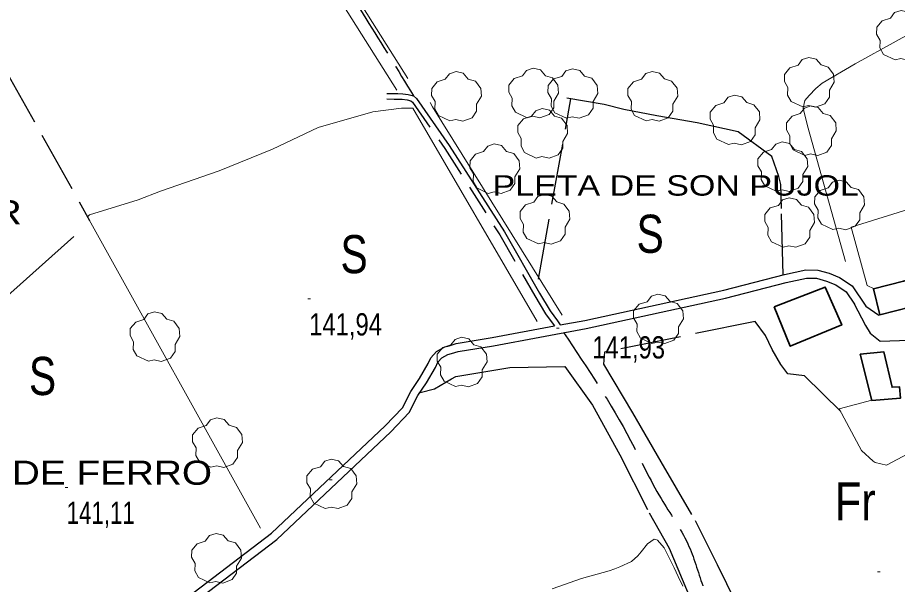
# Model space of a CAD drawing. Extents: x -807245 to 6129983, y -54972206 to 262146364.
# Drawn here: x 488741 to 489087.2, y 4383619.9 to 4383842.8 of the extents above; entities that cross this region are included whole.
import ezdxf
from ezdxf.enums import TextEntityAlignment as Align

# ---------------------------------------------------------------- set-up
doc = ezdxf.new("R2010")
doc.units = 0
doc.header["$LTSCALE"] = 4
doc.linetypes.add('LONG_DASHED', pattern=[7.5, 6, -1.5])
doc.linetypes.add('MEDIUM_DASHED', pattern=[4.5, 3, -1.5])
for name, color, linetype, lineweight in [('25', 7, 'LONG_DASHED', 25), ('27', 7, 'Continuous', 25), ('29', 7, 'Continuous', 13), ('38', 7, 'Continuous', 25), ('47', 7, 'Continuous', 35), ('51', 7, 'Continuous', 13), ('7', 7, 'Continuous', 13), ('9', 7, 'Continuous', 13)]:
    doc.layers.add(name, color=color, linetype=linetype, lineweight=lineweight)
doc.layers.add('31', color=7, linetype='Continuous')
doc.layers.add('5', color=7, linetype='Continuous')

msp = doc.modelspace()

# ---------------------------------------------------------------- linework, layer by layer
at = {"layer": '25'}
msp.add_line((488946.01, 4383739.92), (488958.62, 4383810.82), dxfattribs=at)
for points in [[(488581.61, 4383826.5), (488585.47, 4383840.65), (488589.08, 4383847.74), (488688.78, 4383900.02), (488691.79, 4383901.19), (488769.37, 4383763.08)], [(489042.16, 4383741.69), (489041.52, 4383767.79), (489041.33, 4383777.17), (489040.47, 4383780.34), (489037.71, 4383788.17), (489024.46, 4383797.92), (489008.37, 4383801.41), (488992.57, 4383804.14), (488979.55, 4383806.69), (488971.84, 4383808.65), (488957.09, 4383811.07)], [(489064.84, 4383687.92), (489050.6, 4383701.9), (489044.09, 4383702.72), (489041.35, 4383706.35), (489037.89, 4383712.32), (489035.25, 4383717.83), (489031.19, 4383723.35), (488971.86, 4383711.2), (488971.58, 4383706.47), (488982.99, 4383687.44), (488994.03, 4383668.18), (489007.57, 4383645.07), (489016.3, 4383627.79), (489023.56, 4383612.78), (489032.27, 4383593.77), (489041.51, 4383568.99), (489046.16, 4383555.43), (489052.75, 4383534.95), (489059.24, 4383511.84), (489064.77, 4383489.72), (489070.99, 4383472.64)], [(488899.35, 4383695.4), (488905, 4383696.8), (488911.72, 4383700.7), (488913.46, 4383701.66), (488934.66, 4383705.24), (488956.27, 4383705.67)], [(488956.27, 4383705.67), (488967.2, 4383690.39), (488978, 4383670.84), (488989.45, 4383648.05), (488997.32, 4383634.23), (489005.86, 4383613.88)]]:
    msp.add_lwpolyline(points, dxfattribs=at)
at = {"layer": '27'}
msp.add_spline([(491255.21, 4383970.03), (491244.34, 4383967.52), (491230.36, 4383957.66), (491230.81, 4383957.81), (491230.81, 4383957.81), (491220.15, 4383951.47), (491212.7, 4383943.01), (491205.06, 4383944.23), (491184.85, 4383957.71), (491152.82, 4383981.27), (491128.36, 4384004.58), (491128.29, 4384004.88), (491122.26, 4384021.39), (491095.75, 4384034.59), (491071.07, 4384059.32), (491064.71, 4384065.12)], degree=3, dxfattribs=at)
at = {"layer": '29'}
for points in [[(489086.21, 4383826.19), (489081.67, 4383828.31), (489080.26, 4383830.85), (489080.36, 4383833.83), (489078.99, 4383836.24), (489079.03, 4383838.99), (489081.19, 4383841.59), (489084.38, 4383842.59), (489086.03, 4383844.78), (489088.6, 4383845.61), (489091.46, 4383844.96), (489093.41, 4383842.69), (489096.22, 4383841.87), (489098.35, 4383839.02), (489098.59, 4383835.89), (489096.71, 4383832.74), (489096.71, 4383830.06), (489094.89, 4383827.45), (489091.27, 4383826.11), (489088.5, 4383826.74)], [(489049.91, 4383807.69), (489045.37, 4383809.81), (489043.96, 4383812.35), (489044.06, 4383815.33), (489042.69, 4383817.74), (489042.73, 4383820.49), (489044.89, 4383823.09), (489048.08, 4383824.09), (489049.73, 4383826.28), (489052.3, 4383827.11), (489055.16, 4383826.46), (489057.11, 4383824.19), (489059.92, 4383823.37), (489062.05, 4383820.52), (489062.29, 4383817.39), (489060.41, 4383814.24), (489060.41, 4383811.56), (489058.59, 4383808.95), (489054.97, 4383807.61), (489052.2, 4383808.24)], [(488911.13, 4383802.15), (488906.59, 4383804.27), (488905.18, 4383806.81), (488905.28, 4383809.79), (488903.91, 4383812.2), (488903.95, 4383814.95), (488906.11, 4383817.55), (488909.3, 4383818.55), (488910.95, 4383820.74), (488913.52, 4383821.57), (488916.38, 4383820.92), (488918.33, 4383818.65), (488921.14, 4383817.83), (488923.27, 4383814.98), (488923.51, 4383811.85), (488921.63, 4383808.7), (488921.63, 4383806.02), (488919.81, 4383803.41), (488916.19, 4383802.07), (488913.42, 4383802.7)], [(488941.45, 4383803.45), (488936.91, 4383805.57), (488935.5, 4383808.11), (488935.6, 4383811.09), (488934.23, 4383813.5), (488934.27, 4383816.25), (488936.43, 4383818.85), (488939.62, 4383819.85), (488941.27, 4383822.04), (488943.84, 4383822.87), (488946.7, 4383822.22), (488948.65, 4383819.95), (488951.46, 4383819.13), (488953.59, 4383816.28), (488953.83, 4383813.15), (488951.95, 4383810), (488951.95, 4383807.32), (488950.13, 4383804.71), (488946.51, 4383803.37), (488943.74, 4383804)], [(488956.91, 4383803.28), (488952.37, 4383805.4), (488950.96, 4383807.94), (488951.06, 4383810.92), (488949.69, 4383813.33), (488949.73, 4383816.08), (488951.89, 4383818.68), (488955.08, 4383819.68), (488956.73, 4383821.87), (488959.3, 4383822.7), (488962.16, 4383822.05), (488964.11, 4383819.78), (488966.92, 4383818.96), (488969.05, 4383816.11), (488969.29, 4383812.98), (488967.41, 4383809.83), (488967.41, 4383807.15), (488965.59, 4383804.54), (488961.97, 4383803.2), (488959.2, 4383803.83)], [(488988.33, 4383802.17), (488983.79, 4383804.29), (488982.38, 4383806.83), (488982.48, 4383809.81), (488981.11, 4383812.22), (488981.15, 4383814.97), (488983.31, 4383817.57), (488986.5, 4383818.57), (488988.15, 4383820.76), (488990.72, 4383821.59), (488993.58, 4383820.94), (488995.53, 4383818.67), (488998.34, 4383817.85), (489000.47, 4383815), (489000.71, 4383811.87), (488998.83, 4383808.72), (488998.83, 4383806.04), (488997.01, 4383803.43), (488993.39, 4383802.09), (488990.62, 4383802.72)], [(489020.71, 4383792.87), (489016.17, 4383794.99), (489014.76, 4383797.53), (489014.86, 4383800.51), (489013.49, 4383802.92), (489013.53, 4383805.67), (489015.69, 4383808.27), (489018.88, 4383809.27), (489020.53, 4383811.46), (489023.1, 4383812.29), (489025.96, 4383811.64), (489027.91, 4383809.37), (489030.72, 4383808.55), (489032.85, 4383805.7), (489033.09, 4383802.57), (489031.21, 4383799.42), (489031.21, 4383796.74), (489029.39, 4383794.13), (489025.77, 4383792.79), (489023, 4383793.42)], [(488945.03, 4383787.58), (488940.49, 4383789.7), (488939.08, 4383792.24), (488939.18, 4383795.22), (488937.81, 4383797.63), (488937.85, 4383800.38), (488940.01, 4383802.98), (488943.2, 4383803.98), (488944.85, 4383806.17), (488947.42, 4383807), (488950.28, 4383806.35), (488952.23, 4383804.08), (488955.04, 4383803.26), (488957.17, 4383800.41), (488957.41, 4383797.28), (488955.53, 4383794.13), (488955.53, 4383791.45), (488953.71, 4383788.84), (488950.09, 4383787.5), (488947.32, 4383788.13)], [(489050.74, 4383788.63), (489046.2, 4383790.75), (489044.79, 4383793.29), (489044.89, 4383796.27), (489043.52, 4383798.68), (489043.56, 4383801.43), (489045.72, 4383804.03), (489048.91, 4383805.03), (489050.56, 4383807.22), (489053.13, 4383808.05), (489055.99, 4383807.4), (489057.94, 4383805.13), (489060.75, 4383804.31), (489062.88, 4383801.46), (489063.12, 4383798.33), (489061.24, 4383795.18), (489061.24, 4383792.5), (489059.42, 4383789.89), (489055.8, 4383788.55), (489053.03, 4383789.18)], [(488926.19, 4383773.69), (488921.65, 4383775.81), (488920.24, 4383778.35), (488920.34, 4383781.33), (488918.97, 4383783.74), (488919.01, 4383786.49), (488921.17, 4383789.09), (488924.36, 4383790.09), (488926.01, 4383792.28), (488928.58, 4383793.11), (488931.44, 4383792.46), (488933.39, 4383790.19), (488936.2, 4383789.37), (488938.33, 4383786.52), (488938.57, 4383783.39), (488936.69, 4383780.24), (488936.69, 4383777.56), (488934.87, 4383774.95), (488931.25, 4383773.61), (488928.48, 4383774.24)], [(489039.48, 4383774.5), (489034.94, 4383776.62), (489033.53, 4383779.16), (489033.63, 4383782.14), (489032.26, 4383784.55), (489032.3, 4383787.3), (489034.46, 4383789.9), (489037.65, 4383790.9), (489039.3, 4383793.09), (489041.87, 4383793.92), (489044.73, 4383793.27), (489046.68, 4383791), (489049.49, 4383790.18), (489051.62, 4383787.33), (489051.86, 4383784.2), (489049.98, 4383781.05), (489049.98, 4383778.37), (489048.16, 4383775.76), (489044.54, 4383774.42), (489041.77, 4383775.05)], [(489061.81, 4383759.47), (489057.27, 4383761.59), (489055.86, 4383764.13), (489055.96, 4383767.11), (489054.59, 4383769.52), (489054.63, 4383772.27), (489056.79, 4383774.87), (489059.98, 4383775.87), (489061.63, 4383778.06), (489064.2, 4383778.89), (489067.06, 4383778.24), (489069.01, 4383775.97), (489071.82, 4383775.15), (489073.95, 4383772.3), (489074.19, 4383769.17), (489072.31, 4383766.02), (489072.31, 4383763.34), (489070.49, 4383760.73), (489066.87, 4383759.39), (489064.1, 4383760.02)], [(488945.92, 4383753.81), (488941.38, 4383755.93), (488939.97, 4383758.47), (488940.07, 4383761.45), (488938.7, 4383763.86), (488938.74, 4383766.61), (488940.9, 4383769.21), (488944.09, 4383770.21), (488945.74, 4383772.4), (488948.31, 4383773.23), (488951.17, 4383772.58), (488953.12, 4383770.31), (488955.93, 4383769.49), (488958.06, 4383766.64), (488958.3, 4383763.51), (488956.42, 4383760.36), (488956.42, 4383757.68), (488954.6, 4383755.07), (488950.98, 4383753.73), (488948.21, 4383754.36)], [(489042.16, 4383752.57), (489037.62, 4383754.69), (489036.21, 4383757.23), (489036.31, 4383760.21), (489034.94, 4383762.62), (489034.98, 4383765.37), (489037.14, 4383767.97), (489040.33, 4383768.97), (489041.98, 4383771.16), (489044.55, 4383771.99), (489047.41, 4383771.34), (489049.36, 4383769.07), (489052.17, 4383768.25), (489054.3, 4383765.4), (489054.54, 4383762.27), (489052.66, 4383759.12), (489052.66, 4383756.44), (489050.84, 4383753.83), (489047.22, 4383752.49), (489044.45, 4383753.12)], [(488990.56, 4383714.67), (488986.02, 4383716.79), (488984.61, 4383719.33), (488984.71, 4383722.31), (488983.34, 4383724.72), (488983.38, 4383727.47), (488985.54, 4383730.07), (488988.73, 4383731.07), (488990.38, 4383733.26), (488992.95, 4383734.09), (488995.81, 4383733.44), (488997.76, 4383731.17), (489000.57, 4383730.35), (489002.7, 4383727.5), (489002.94, 4383724.37), (489001.06, 4383721.22), (489001.06, 4383718.54), (488999.24, 4383715.93), (488995.62, 4383714.59), (488992.85, 4383715.22)], [(488792.5, 4383707.69), (488787.96, 4383709.81), (488786.55, 4383712.35), (488786.65, 4383715.33), (488785.28, 4383717.74), (488785.32, 4383720.49), (488787.48, 4383723.09), (488790.67, 4383724.09), (488792.32, 4383726.28), (488794.89, 4383727.11), (488797.75, 4383726.46), (488799.7, 4383724.19), (488802.51, 4383723.37), (488804.64, 4383720.52), (488804.88, 4383717.39), (488803, 4383714.24), (488803, 4383711.56), (488801.18, 4383708.95), (488797.56, 4383707.61), (488794.79, 4383708.24)], [(488913.32, 4383697.69), (488908.78, 4383699.81), (488907.37, 4383702.35), (488907.47, 4383705.33), (488906.1, 4383707.74), (488906.14, 4383710.49), (488908.3, 4383713.09), (488911.49, 4383714.09), (488913.14, 4383716.28), (488915.71, 4383717.11), (488918.57, 4383716.46), (488920.52, 4383714.19), (488923.33, 4383713.37), (488925.46, 4383710.52), (488925.7, 4383707.39), (488923.82, 4383704.24), (488923.82, 4383701.56), (488922, 4383698.95), (488918.38, 4383697.61), (488915.61, 4383698.24)], [(488817.08, 4383666), (488812.54, 4383668.12), (488811.13, 4383670.66), (488811.23, 4383673.64), (488809.86, 4383676.05), (488809.9, 4383678.8), (488812.06, 4383681.4), (488815.25, 4383682.4), (488816.9, 4383684.59), (488819.47, 4383685.42), (488822.33, 4383684.77), (488824.28, 4383682.5), (488827.09, 4383681.68), (488829.22, 4383678.83), (488829.46, 4383675.7), (488827.58, 4383672.55), (488827.58, 4383669.87), (488825.76, 4383667.26), (488822.14, 4383665.92), (488819.37, 4383666.55)], [(488862.06, 4383649.81), (488857.52, 4383651.93), (488856.11, 4383654.47), (488856.21, 4383657.45), (488854.84, 4383659.86), (488854.88, 4383662.61), (488857.04, 4383665.21), (488860.23, 4383666.21), (488861.88, 4383668.4), (488864.45, 4383669.23), (488867.31, 4383668.58), (488869.26, 4383666.31), (488872.07, 4383665.49), (488874.2, 4383662.64), (488874.44, 4383659.51), (488872.56, 4383656.36), (488872.56, 4383653.68), (488870.74, 4383651.07), (488867.12, 4383649.73), (488864.35, 4383650.36)], [(488816.71, 4383620.54), (488812.17, 4383622.66), (488810.76, 4383625.2), (488810.86, 4383628.18), (488809.49, 4383630.59), (488809.53, 4383633.34), (488811.69, 4383635.94), (488814.88, 4383636.94), (488816.53, 4383639.13), (488819.1, 4383639.96), (488821.96, 4383639.31), (488823.91, 4383637.04), (488826.72, 4383636.22), (488828.85, 4383633.37), (488829.09, 4383630.24), (488827.21, 4383627.09), (488827.21, 4383624.41), (488825.39, 4383621.8), (488821.77, 4383620.46), (488819, 4383621.09)]]:
    msp.add_lwpolyline(points, close=True, dxfattribs=at)
at = {"layer": '38'}
for points in [[(488886.29, 4383812.95), (488889.15, 4383812.92), (488890.59, 4383812.9), (488892.55, 4383812.81), (488894.69, 4383812.54), (488896.74, 4383812.06), (488898.02, 4383810.97), (488910.83, 4383792.5), (488932.53, 4383758.51), (488946.3, 4383734.48), (488950.53, 4383727.53), (488953.48, 4383723.53), (488954.49, 4383721.95)], [(488751.62, 4383567.92), (488789.76, 4383597.05), (488843.03, 4383637.6), (488887.89, 4383679.96), (488895.08, 4383687.46), (488898.54, 4383694.17), (488901.86, 4383699.2), (488905.38, 4383705.28), (488906.3, 4383707.26), (488907.87, 4383708.98), (488910.28, 4383710.27), (488911.71, 4383710.66), (488914.41, 4383711.57), (488928.26, 4383713.8), (488964.77, 4383720.59), (489019.58, 4383732.51), (489043.43, 4383738.69), (489051.39, 4383740.35), (489055.38, 4383740.31), (489059.3, 4383739.22), (489062.91, 4383737.71), (489067.01, 4383734.96), (489070.32, 4383730.1)], [(488954.49, 4383721.95), (488964.13, 4383723.75), (489018.84, 4383735.65), (489042.69, 4383741.83), (489051.07, 4383743.58), (489055.84, 4383743.52), (489060.36, 4383742.27), (489064.44, 4383740.57), (489069.32, 4383737.29), (489074.73, 4383729.33), (489079.91, 4383725.8)], [(489070.05, 4383730.5), (489074.61, 4383721.73), (489076.38, 4383718.71), (489080.39, 4383715.59), (489099.53, 4383716.27), (489102.45, 4383716.09), (489107.55, 4383715.95), (489110.84, 4383715.02), (489114.24, 4383710.4), (489115.12, 4383708.22), (489115.7, 4383706.71), (489116.86, 4383703.39)], [(488749.66, 4383570.48), (488787.8, 4383599.61), (488840.94, 4383640.07), (488885.62, 4383682.25), (488892.43, 4383689.35), (488895.75, 4383695.8), (488899.12, 4383700.9), (488902.52, 4383706.76), (488903.58, 4383709.06), (488905.86, 4383711.56), (488909.08, 4383713.29), (488910.77, 4383713.75), (488913.63, 4383714.71), (488927.71, 4383716.98), (488952.22, 4383721.54)]]:
    msp.add_lwpolyline(points, dxfattribs=at)
at = {"layer": '38', "linetype": 'MEDIUM_DASHED'}
msp.add_lwpolyline([(488886.27, 4383810.82), (488889.12, 4383810.79), (488890.53, 4383810.77), (488892.37, 4383810.68), (488894.32, 4383810.44), (488895.75, 4383810.1), (488896.43, 4383809.52), (488909.06, 4383791.31), (488930.71, 4383757.4), (488944.46, 4383733.4), (488948.76, 4383726.34), (488951.72, 4383722.32), (488952.22, 4383721.54)], dxfattribs=at)
at = {"layer": '38', "linetype": 'LONG_DASHED'}
for points in [[(488695.06, 4384126.59), (488710.74, 4384102.85), (488739.13, 4384059.92), (488761.9, 4384023.12), (488787.39, 4383981.87), (488812.68, 4383943.17), (488842.39, 4383897.3), (488878.08, 4383842.43), (488896.74, 4383812.06)], [(488955.84, 4383718.93), (488982.19, 4383676.49), (488994.16, 4383653.7), (489004.69, 4383635.88), (489010.58, 4383619.45), (489020.22, 4383596.54), (489030.59, 4383571.89), (489036.84, 4383553.59), (489043.46, 4383535.81), (489049.64, 4383512.03), (489055.75, 4383487.95), (489061.98, 4383468.82), (489067.02, 4383449.79), (489070.82, 4383428.51), (489074.72, 4383407.91), (489078.13, 4383385.07), (489080.63, 4383367.11), (489082.86, 4383338.57), (489084.43, 4383298.57), (489086.67, 4383251.81), (489090.1, 4383204.28), (489089.96, 4383184.77)]]:
    msp.add_spline(points, degree=3, dxfattribs=at)
at = {"layer": '47'}
for points in [[(489077.77, 4383736.1), (489089.51, 4383739.12), (489114.57, 4383745.96), (489114.37, 4383747.84), (489125.81, 4383751.16), (489127.74, 4383743.11), (489121.88, 4383742.27), (489123.48, 4383737.38), (489116.11, 4383736.04), (489116.18, 4383735.36), (489109.62, 4383732.96), (489098.56, 4383730.16), (489092.55, 4383729.03), (489080.21, 4383725.87)], [(489038.68, 4383729.12), (489058.8, 4383736.84), (489065.24, 4383721.99), (489045.03, 4383713.59)], [(489072.53, 4383710.43), (489077.13, 4383692.22), (489088.39, 4383693.21), (489087.92, 4383697.65), (489085.06, 4383697.45), (489081.84, 4383711.37)]]:
    msp.add_lwpolyline(points, close=True, dxfattribs=at)
at = {"layer": '51'}
msp.add_line((488763.14, 4383756.78), (488665.94, 4383670.09), dxfattribs=at)
for points in [[(488692.03, 4384126.59), (488771.71, 4384002.16), (488890.28, 4383814.23)], [(488699.24, 4384126.58), (488775.97, 4384006.76), (488894.54, 4383818.83)], [(489102.84, 4383842.49), (489070.53, 4383824.63), (489057.54, 4383817.05), (489055.11, 4383814.9), (489052.46, 4383812.16), (489050.78, 4383810.15), (489050.08, 4383807.23), (489051.8, 4383800.24), (489066.8, 4383746.95)], [(488955.22, 4383725.86), (488904.24, 4383807.77), (488903.36, 4383809.43)], [(488945.44, 4383723.35), (488896.58, 4383807.25), (488892, 4383807.23), (488880.81, 4383805.78), (488859.28, 4383799.58), (488841.33, 4383791.08), (488820.38, 4383782.54), (488797.26, 4383774.55), (488788.44, 4383771.12), (488769.32, 4383765.26), (488768.56, 4383764.52), (488836.63, 4383641.99)], [(489077.97, 4383736.15), (489075.24, 4383737.48), (489068.9, 4383760.43), (489120.62, 4383776.5), (489126.95, 4383757.82)], [(489077.09, 4383692.37), (489064.26, 4383688.99), (489073, 4383672.61), (489077.68, 4383668.43), (489078.42, 4383667.9), (489082.91, 4383666.79)], [(489082.91, 4383666.79), (489127.07, 4383690.22), (489149.09, 4383641.06), (489155.71, 4383627.33)]]:
    msp.add_lwpolyline(points, dxfattribs=at)
at = {"layer": '7'}
for p, q in [((488855.24, 4383732.17), (488856.24, 4383732.17)), ((488953.09, 4383720.63), (488954.09, 4383720.63)), ((488863.73, 4383661.11), (488864.73, 4383661.11)), ((488759.8, 4383658.09), (488760.8, 4383658.09)), ((489079.39, 4383624.89), (489080.39, 4383624.89))]:
    msp.add_line(p, q, dxfattribs=at)
at = {"layer": '9'}
msp.add_lwpolyline([(489002.71, 4383619.18), (489000.92, 4383623.05), (488999.35, 4383626.41), (488995.38, 4383634.33), (488992.81, 4383637.36), (488992.1, 4383637.64), (488991.4, 4383637.68), (488988.89, 4383635.82), (488986.39, 4383632.68), (488985.7, 4383631.91), (488985.01, 4383631.2), (488982.5, 4383628.99), (488977.97, 4383626.79), (488976, 4383626.08), (488973.73, 4383625.32), (488962.93, 4383622.19), (488951.33, 4383618.22)], dxfattribs=at)

# ---------------------------------------------------------------- texts
at = {"layer": '31'}
for s, width, p in [('S', 0.8, (488989.89, 4383750.3)), ('S', 0.8, (488873.41, 4383742.29)), ('S', 0.8, (488750.84, 4383694.38)), ('Fr', 0.85, (489070.56, 4383645.07))]:
    msp.add_text(s, height=15, dxfattribs=dict(at, width=width)).set_placement(p, align=Align.CENTER)
at = {"layer": '5'}
for s, height, width, p in [('PLETA DE SON PUJOL', 8, 1.25, (489072.02, 4383772.8)), ("SA COPA D'OR", 9.5, 1.25, (488742.71, 4383761.57)), ('TANCA DE FERRO', 9.5, 1.2, (488817.53, 4383659.1))]:
    msp.add_text(s, height=height, dxfattribs=dict(at, width=width)).set_placement(p, align=Align.RIGHT)
at = {"layer": '7'}
for s, width, p in [('141,94', 0.8, (488855.74, 4383717.8)), ('141,93', 0.8, (488967.11, 4383708.76)), ('141,11', 0.75, (488760.3, 4383643.72))]:
    msp.add_text(s, height=8.75, dxfattribs=dict(at, width=width)).set_placement(p)

doc.saveas('drawing.dxf')
